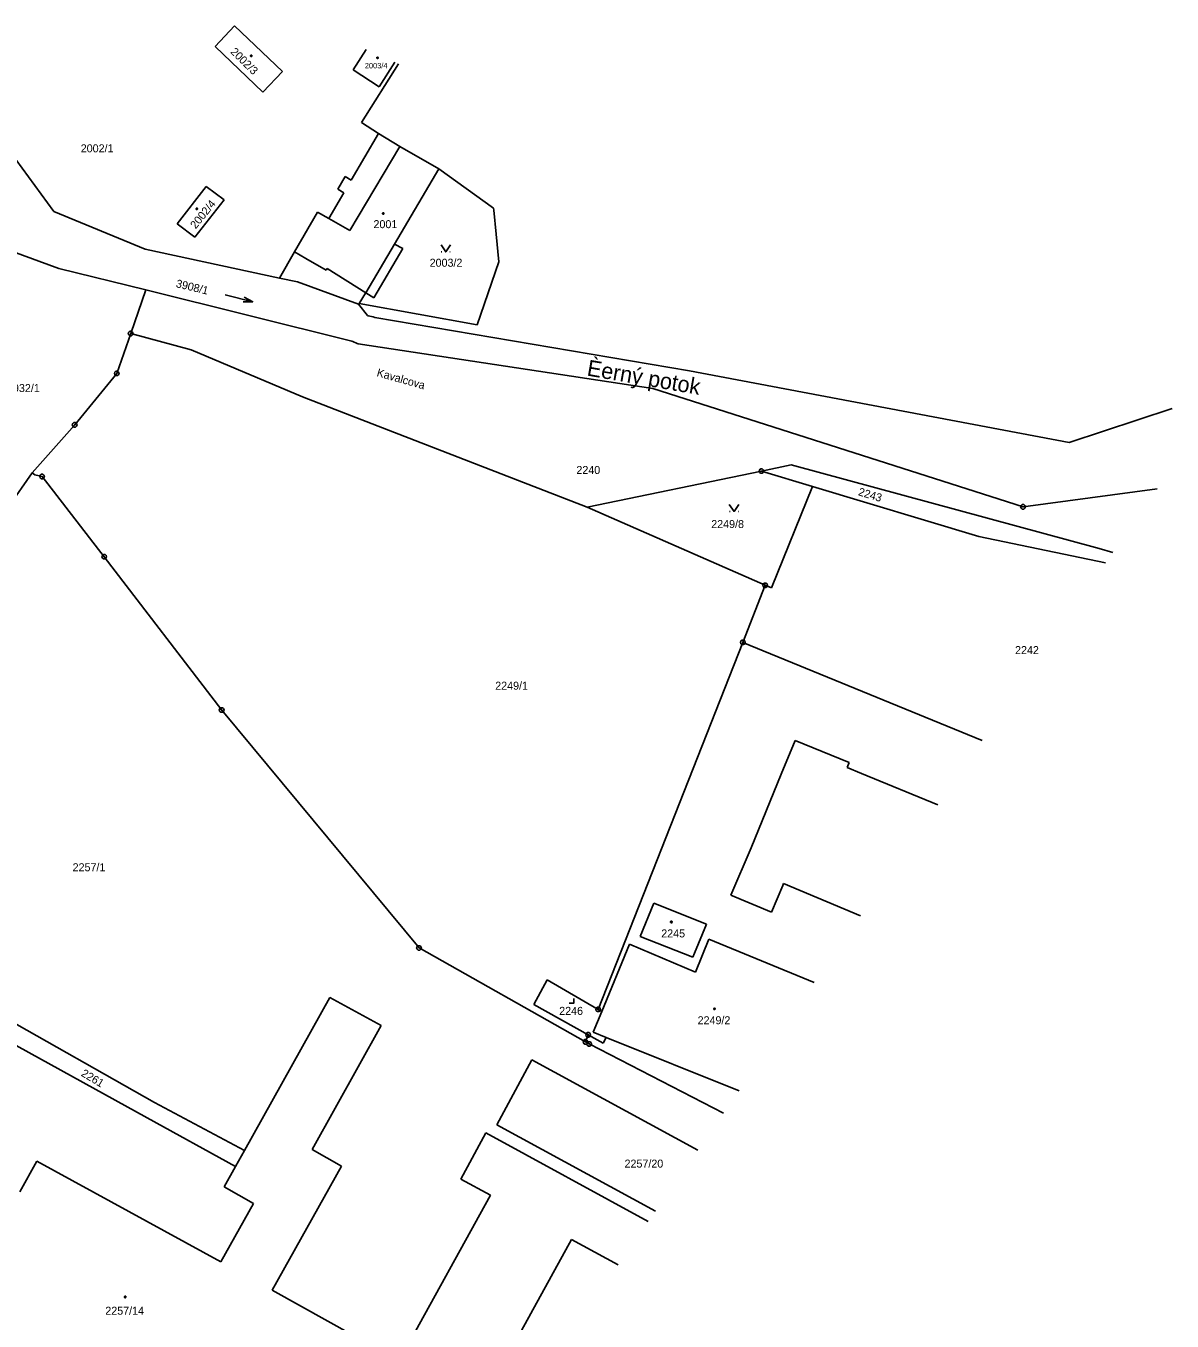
# Model space of a CAD drawing. Extents: x -528274 to -527531, y -1079304 to -1078580.
# Drawn here: x -527864 to -527620.7, y -1078911.9 to -1078636.8 of the extents above; entities that cross this region are included whole.
import ezdxf

# ---------------------------------------------------------------- set-up
doc = ezdxf.new("R2010")
doc.units = 0
doc.layers.add('katastrální mapa', color=7, linetype='Continuous')

msp = doc.modelspace()

# ---------------------------------------------------------------- linework, layer by layer
at = {"layer": 'katastrální mapa'}
for p, q in [((-527823.8, -1078641.21), (-527819.71, -1078636.82)), ((-527819.71, -1078636.82), (-527809.51, -1078646.52)), ((-527813.68, -1078650.87), (-527823.8, -1078641.21)), ((-527794.54, -1078646.16), (-527791.74, -1078641.84)), ((-527784.88, -1078644.89), (-527792.77, -1078657.34)), ((-527785.66, -1078644.54), (-527788.99, -1078649.73)), ((-527809.51, -1078646.52), (-527813.68, -1078650.87)), ((-527788.99, -1078649.73), (-527794.54, -1078646.16)), ((-527874.15, -1078654.27), (-527858.07, -1078676.23)), ((-527792.77, -1078657.34), (-527789.17, -1078659.65)), ((-527794.92, -1078669.55), (-527789.17, -1078659.65)), ((-527789.17, -1078659.65), (-527784.61, -1078662.4)), ((-527795.21, -1078680.24), (-527784.61, -1078662.4)), ((-527784.61, -1078662.4), (-527776.34, -1078667.2)), ((-527776.34, -1078667.2), (-527785.75, -1078683.15)), ((-527764.72, -1078675.54), (-527776.34, -1078667.2)), ((-527797.77, -1078671.52), (-527796.2, -1078668.81)), ((-527796.2, -1078668.81), (-527794.92, -1078669.55)), ((-527831.85, -1078678.83), (-527825.7, -1078670.92)), ((-527825.7, -1078670.92), (-527821.93, -1078673.78)), ((-527799.68, -1078677.73), (-527796.5, -1078672.26)), ((-527796.5, -1078672.26), (-527797.77, -1078671.52)), ((-527821.93, -1078673.78), (-527828.11, -1078681.68)), ((-527764.68, -1078675.95), (-527764.72, -1078675.54)), ((-527858.07, -1078676.23), (-527838.69, -1078684.25)), ((-527806.97, -1078684.81), (-527802.12, -1078676.36)), ((-527802.12, -1078676.36), (-527799.68, -1078677.73)), ((-527795.21, -1078680.24), (-527799.68, -1078677.73)), ((-527764.17, -1078681.04), (-527764.68, -1078675.95)), ((-527828.11, -1078681.68), (-527831.85, -1078678.83)), ((-527763.59, -1078686.89), (-527764.17, -1078681.04)), ((-527785.75, -1078683.15), (-527791.85, -1078693.49)), ((-527785.75, -1078683.15), (-527783.99, -1078684.07)), ((-527856.97, -1078688.3), (-527866.85, -1078684.72)), ((-527838.69, -1078684.25), (-527810.16, -1078690.36)), ((-527810.16, -1078690.36), (-527806.97, -1078684.81)), ((-527804.59, -1078686.18), (-527806.97, -1078684.81)), ((-527800.23, -1078688.72), (-527804.59, -1078686.18)), ((-527783.99, -1078684.07), (-527790.11, -1078694.59)), ((-527775.83, -1078684.83), (-527775.73, -1078684.83)), ((-527774.03, -1078684.83), (-527773.93, -1078684.83)), ((-527838.52, -1078692.88), (-527856.97, -1078688.3)), ((-527800.23, -1078688.72), (-527800.03, -1078688.36)), ((-527800.03, -1078688.36), (-527791.85, -1078693.49)), ((-527768.2, -1078700.28), (-527763.59, -1078686.89)), ((-527806.37, -1078691.17), (-527810.16, -1078690.36)), ((-527793.39, -1078695.94), (-527806.37, -1078691.17)), ((-527841.75, -1078702.14), (-527838.52, -1078692.88)), ((-527838.52, -1078692.88), (-527794.83, -1078703.76)), ((-527821.66, -1078693.92), (-527815.84, -1078695.38)), ((-527791.89, -1078693.56), (-527793.28, -1078695.76)), ((-527791.85, -1078693.49), (-527791.89, -1078693.56)), ((-527790.11, -1078694.59), (-527791.85, -1078693.49)), ((-527793.28, -1078695.76), (-527793.39, -1078695.94)), ((-527793.39, -1078695.94), (-527791.48, -1078698.33)), ((-527793.28, -1078695.76), (-527768.2, -1078700.28)), ((-527791.48, -1078698.33), (-527791.31, -1078698.37)), ((-527791.31, -1078698.37), (-527790.27, -1078698.62)), ((-527790.27, -1078698.62), (-527789.92, -1078698.71)), ((-527789.92, -1078698.71), (-527723.14, -1078710.07)), ((-527844.71, -1078710.62), (-527841.75, -1078702.14)), ((-527841.87, -1078702.14), (-527841.63, -1078702.14)), ((-527828.93, -1078705.6), (-527841.75, -1078702.14)), ((-527805.27, -1078715.6), (-527828.93, -1078705.6)), ((-527794.83, -1078703.76), (-527794.61, -1078703.85)), ((-527794.61, -1078703.85), (-527793.7, -1078704.24)), ((-527793.7, -1078704.24), (-527793.43, -1078704.35)), ((-527793.43, -1078704.35), (-527730.93, -1078713.79)), ((-527844.71, -1078710.62), (-527853.64, -1078721.55)), ((-527844.83, -1078710.62), (-527844.59, -1078710.62)), ((-527723.14, -1078710.07), (-527642.54, -1078725.25)), ((-527730.93, -1078713.79), (-527652.33, -1078738.95)), ((-527744.86, -1078739.03), (-527805.27, -1078715.6)), ((-527642.54, -1078725.25), (-527620.69, -1078718.06)), ((-527853.64, -1078721.55), (-527862.64, -1078731.72)), ((-527853.76, -1078721.55), (-527853.52, -1078721.55)), ((-527707.86, -1078731.36), (-527701.52, -1078730.04)), ((-527636.16, -1078747.81), (-527701.52, -1078730.04)), ((-527867.72, -1078738.94), (-527862.64, -1078731.72)), ((-527862.64, -1078731.72), (-527862.11, -1078732.12)), ((-527862.11, -1078732.12), (-527860.56, -1078732.51)), ((-527860.68, -1078732.51), (-527860.44, -1078732.51)), ((-527860.56, -1078732.51), (-527847.35, -1078749.55)), ((-527744.86, -1078739.03), (-527707.86, -1078731.36)), ((-527707.98, -1078731.36), (-527707.74, -1078731.36)), ((-527707.86, -1078731.36), (-527697.04, -1078734.64)), ((-527697.04, -1078734.64), (-527705.76, -1078756.16)), ((-527697.04, -1078734.64), (-527661.74, -1078745.23)), ((-527652.33, -1078738.95), (-527623.88, -1078735.11)), ((-527652.45, -1078738.95), (-527652.21, -1078738.95)), ((-527707.06, -1078755.61), (-527744.86, -1078739.03)), ((-527714.63, -1078739.93), (-527714.53, -1078739.93)), ((-527712.83, -1078739.93), (-527712.73, -1078739.93)), ((-527661.74, -1078745.23), (-527634.82, -1078750.87)), ((-527847.47, -1078749.55), (-527847.23, -1078749.55)), ((-527847.35, -1078749.55), (-527822.43, -1078782.1)), ((-527633.29, -1078748.65), (-527636.16, -1078747.81)), ((-527707.06, -1078755.61), (-527711.81, -1078767.73)), ((-527707.18, -1078755.61), (-527706.94, -1078755.61)), ((-527705.76, -1078756.16), (-527707.06, -1078755.61)), ((-527711.81, -1078767.73), (-527742.5, -1078845.67)), ((-527711.93, -1078767.73), (-527711.69, -1078767.73)), ((-527711.81, -1078767.73), (-527661.01, -1078788.59)), ((-527822.55, -1078782.1), (-527822.31, -1078782.1)), ((-527822.43, -1078782.1), (-527780.54, -1078832.62)), ((-527703.65, -1078795.72), (-527700.73, -1078788.57)), ((-527700.73, -1078788.57), (-527689.23, -1078793.27)), ((-527689.23, -1078793.27), (-527689.66, -1078794.33)), ((-527710.06, -1078811.38), (-527703.65, -1078795.72)), ((-527689.66, -1078794.33), (-527686.65, -1078795.56)), ((-527686.65, -1078795.56), (-527670.44, -1078802.19)), ((-527714.35, -1078821.4), (-527710.06, -1078811.38)), ((-527916.26, -1078820.33), (-527836.7, -1078865.44)), ((-527705.73, -1078825.02), (-527714.35, -1078821.4)), ((-527703.34, -1078819.36), (-527705.73, -1078825.02)), ((-527703.17, -1078818.96), (-527703.34, -1078819.36)), ((-527686.84, -1078825.82), (-527703.17, -1078818.96)), ((-527733.59, -1078830.21), (-527730.67, -1078823.13)), ((-527730.67, -1078823.13), (-527719.53, -1078827.54)), ((-527918.51, -1078824.42), (-527838.26, -1078868.7)), ((-527719.53, -1078827.54), (-527722.08, -1078833.74)), ((-527741.77, -1078846.09), (-527735.9, -1078831.82)), ((-527735.9, -1078831.82), (-527721.88, -1078837.74)), ((-527722.43, -1078834.59), (-527733.59, -1078830.21)), ((-527721.88, -1078837.74), (-527719, -1078830.73)), ((-527719, -1078830.73), (-527696.66, -1078839.97)), ((-527780.66, -1078832.62), (-527780.42, -1078832.62)), ((-527780.54, -1078832.62), (-527745.22, -1078852.56)), ((-527722.08, -1078833.74), (-527722.43, -1078834.59)), ((-527756.16, -1078844.61), (-527753.35, -1078839.42)), ((-527753.35, -1078839.42), (-527742.5, -1078845.67)), ((-527799.48, -1078843.12), (-527817.58, -1078875.62)), ((-527788.61, -1078849.08), (-527799.48, -1078843.12)), ((-527756.16, -1078844.61), (-527744.63, -1078851.07)), ((-527741.77, -1078846.09), (-527743.58, -1078850.49)), ((-527742.62, -1078845.67), (-527742.38, -1078845.67)), ((-527742.5, -1078845.67), (-527741.77, -1078846.09)), ((-527803.23, -1078875.43), (-527788.61, -1078849.08)), ((-527744.63, -1078851.07), (-527745.22, -1078852.56)), ((-527744.75, -1078851.07), (-527744.51, -1078851.07)), ((-527744.63, -1078851.07), (-527741.47, -1078852.84)), ((-527743.58, -1078850.49), (-527740.8, -1078851.6)), ((-527740.8, -1078851.6), (-527741.47, -1078852.84)), ((-527712.62, -1078862.96), (-527740.8, -1078851.6)), ((-527745.34, -1078852.56), (-527745.1, -1078852.56)), ((-527745.22, -1078852.56), (-527744.43, -1078853.01)), ((-527744.55, -1078853.01), (-527744.31, -1078853.01)), ((-527744.43, -1078853.01), (-527715.93, -1078867.73)), ((-527756.59, -1078856.4), (-527764.02, -1078870.15)), ((-527721.39, -1078875.59), (-527756.59, -1078856.4)), ((-527836.7, -1078865.44), (-527817.58, -1078875.62)), ((-527838.26, -1078868.7), (-527819.47, -1078879)), ((-527764.02, -1078870.15), (-527730.35, -1078888.5)), ((-527766.35, -1078871.89), (-527771.66, -1078881.69)), ((-527731.87, -1078890.69), (-527766.35, -1078871.89)), ((-527817.58, -1078875.62), (-527819.47, -1078879)), ((-527796.99, -1078878.94), (-527803.23, -1078875.43)), ((-527861.67, -1078877.91), (-527865.29, -1078884.42)), ((-527822.64, -1078899.28), (-527861.67, -1078877.91)), ((-527819.47, -1078879), (-527821.9, -1078883.37)), ((-527811.7, -1078905.31), (-527796.99, -1078878.94)), ((-527771.66, -1078881.69), (-527765.36, -1078885.09)), ((-527821.9, -1078883.37), (-527815.66, -1078886.85)), ((-527815.66, -1078886.85), (-527822.64, -1078899.28)), ((-527765.36, -1078885.09), (-527784.77, -1078920.26)), ((-527767.53, -1078929.65), (-527748.19, -1078894.51)), ((-527748.19, -1078894.51), (-527738.28, -1078899.92)), ((-527784.77, -1078920.26), (-527811.7, -1078905.31))]:
    msp.add_line(p, q, dxfattribs=at)
for points in [[(-527816.15, -1078643.01), (-527816.05, -1078643.03), (-527816, -1078643.12), (-527815.98, -1078643.18), (-527816, -1078643.27), (-527816.08, -1078643.34), (-527816.15, -1078643.35), (-527816.24, -1078643.32), (-527816.3, -1078643.26), (-527816.32, -1078643.18), (-527816.3, -1078643.09), (-527816.22, -1078643.02)], [(-527789.36, -1078643.42), (-527789.26, -1078643.44), (-527789.21, -1078643.53), (-527789.19, -1078643.59), (-527789.21, -1078643.68), (-527789.29, -1078643.75), (-527789.36, -1078643.76), (-527789.45, -1078643.73), (-527789.51, -1078643.67), (-527789.53, -1078643.59), (-527789.51, -1078643.5), (-527789.43, -1078643.43)], [(-527827.72, -1078675.5), (-527827.62, -1078675.52), (-527827.57, -1078675.61), (-527827.55, -1078675.67), (-527827.57, -1078675.76), (-527827.65, -1078675.83), (-527827.72, -1078675.84), (-527827.81, -1078675.81), (-527827.87, -1078675.75), (-527827.89, -1078675.67), (-527827.87, -1078675.58), (-527827.79, -1078675.51)], [(-527788.13, -1078676.5), (-527788.03, -1078676.52), (-527787.98, -1078676.61), (-527787.96, -1078676.67), (-527787.98, -1078676.76), (-527788.06, -1078676.83), (-527788.13, -1078676.84), (-527788.22, -1078676.81), (-527788.28, -1078676.75), (-527788.3, -1078676.67), (-527788.28, -1078676.58), (-527788.2, -1078676.51)], [(-527841.6, -1078701.66), (-527841.35, -1078701.84), (-527841.25, -1078702.13), (-527841.35, -1078702.42), (-527841.6, -1078702.6), (-527841.91, -1078702.6), (-527842.16, -1078702.42), (-527842.26, -1078702.13), (-527842.16, -1078701.84), (-527841.91, -1078701.66)], [(-527844.56, -1078710.14), (-527844.31, -1078710.32), (-527844.21, -1078710.61), (-527844.31, -1078710.9), (-527844.56, -1078711.08), (-527844.87, -1078711.08), (-527845.12, -1078710.9), (-527845.22, -1078710.61), (-527845.12, -1078710.32), (-527844.87, -1078710.14)], [(-527853.49, -1078721.07), (-527853.24, -1078721.25), (-527853.14, -1078721.54), (-527853.24, -1078721.83), (-527853.49, -1078722.01), (-527853.8, -1078722.01), (-527854.05, -1078721.83), (-527854.15, -1078721.54), (-527854.05, -1078721.25), (-527853.8, -1078721.07)], [(-527860.41, -1078732.03), (-527860.16, -1078732.21), (-527860.06, -1078732.5), (-527860.16, -1078732.79), (-527860.41, -1078732.97), (-527860.72, -1078732.97), (-527860.97, -1078732.79), (-527861.07, -1078732.5), (-527860.97, -1078732.21), (-527860.72, -1078732.03)], [(-527707.71, -1078730.88), (-527707.46, -1078731.06), (-527707.36, -1078731.35), (-527707.46, -1078731.64), (-527707.71, -1078731.82), (-527708.02, -1078731.82), (-527708.27, -1078731.64), (-527708.37, -1078731.35), (-527708.27, -1078731.06), (-527708.02, -1078730.88)], [(-527652.18, -1078738.47), (-527651.93, -1078738.65), (-527651.83, -1078738.94), (-527651.93, -1078739.23), (-527652.18, -1078739.41), (-527652.49, -1078739.41), (-527652.74, -1078739.23), (-527652.84, -1078738.94), (-527652.74, -1078738.65), (-527652.49, -1078738.47)], [(-527847.2, -1078749.07), (-527846.95, -1078749.25), (-527846.85, -1078749.54), (-527846.95, -1078749.83), (-527847.2, -1078750.01), (-527847.51, -1078750.01), (-527847.76, -1078749.83), (-527847.86, -1078749.54), (-527847.76, -1078749.25), (-527847.51, -1078749.07)], [(-527706.91, -1078755.13), (-527706.66, -1078755.31), (-527706.56, -1078755.6), (-527706.66, -1078755.89), (-527706.91, -1078756.07), (-527707.22, -1078756.07), (-527707.47, -1078755.89), (-527707.57, -1078755.6), (-527707.47, -1078755.31), (-527707.22, -1078755.13)], [(-527711.66, -1078767.25), (-527711.41, -1078767.43), (-527711.31, -1078767.72), (-527711.41, -1078768.01), (-527711.66, -1078768.19), (-527711.97, -1078768.19), (-527712.22, -1078768.01), (-527712.32, -1078767.72), (-527712.22, -1078767.43), (-527711.97, -1078767.25)], [(-527822.28, -1078781.62), (-527822.03, -1078781.8), (-527821.93, -1078782.09), (-527822.03, -1078782.38), (-527822.28, -1078782.56), (-527822.59, -1078782.56), (-527822.84, -1078782.38), (-527822.94, -1078782.09), (-527822.84, -1078781.8), (-527822.59, -1078781.62)], [(-527726.99, -1078826.93), (-527726.89, -1078826.95), (-527726.84, -1078827.04), (-527726.82, -1078827.1), (-527726.84, -1078827.19), (-527726.92, -1078827.26), (-527726.99, -1078827.27), (-527727.08, -1078827.24), (-527727.14, -1078827.18), (-527727.16, -1078827.1), (-527727.14, -1078827.01), (-527727.06, -1078826.94)], [(-527780.39, -1078832.14), (-527780.14, -1078832.32), (-527780.04, -1078832.61), (-527780.14, -1078832.9), (-527780.39, -1078833.08), (-527780.7, -1078833.08), (-527780.95, -1078832.9), (-527781.05, -1078832.61), (-527780.95, -1078832.32), (-527780.7, -1078832.14)], [(-527742.35, -1078845.19), (-527742.1, -1078845.37), (-527742, -1078845.66), (-527742.1, -1078845.95), (-527742.35, -1078846.13), (-527742.66, -1078846.13), (-527742.91, -1078845.95), (-527743.01, -1078845.66), (-527742.91, -1078845.37), (-527742.66, -1078845.19)], [(-527717.85, -1078845.36), (-527717.75, -1078845.38), (-527717.7, -1078845.47), (-527717.68, -1078845.53), (-527717.7, -1078845.62), (-527717.78, -1078845.69), (-527717.85, -1078845.7), (-527717.94, -1078845.67), (-527718, -1078845.61), (-527718.02, -1078845.53), (-527718, -1078845.44), (-527717.92, -1078845.37)], [(-527744.48, -1078850.59), (-527744.23, -1078850.77), (-527744.13, -1078851.06), (-527744.23, -1078851.35), (-527744.48, -1078851.53), (-527744.79, -1078851.53), (-527745.04, -1078851.35), (-527745.14, -1078851.06), (-527745.04, -1078850.77), (-527744.79, -1078850.59)], [(-527745.07, -1078852.08), (-527744.82, -1078852.26), (-527744.72, -1078852.55), (-527744.82, -1078852.84), (-527745.07, -1078853.02), (-527745.38, -1078853.02), (-527745.63, -1078852.84), (-527745.73, -1078852.55), (-527745.63, -1078852.26), (-527745.38, -1078852.08)], [(-527744.28, -1078852.53), (-527744.03, -1078852.71), (-527743.93, -1078853), (-527744.03, -1078853.29), (-527744.28, -1078853.47), (-527744.59, -1078853.47), (-527744.84, -1078853.29), (-527744.94, -1078853), (-527744.84, -1078852.71), (-527744.59, -1078852.53)], [(-527842.91, -1078906.57), (-527842.81, -1078906.59), (-527842.76, -1078906.68), (-527842.74, -1078906.74), (-527842.76, -1078906.83), (-527842.84, -1078906.9), (-527842.91, -1078906.91), (-527843, -1078906.88), (-527843.06, -1078906.82), (-527843.08, -1078906.74), (-527843.06, -1078906.65), (-527842.98, -1078906.58)]]:
    msp.add_lwpolyline(points, close=True, dxfattribs=at)
for points in [[(-527775.88, -1078683.33), (-527774.88, -1078684.83), (-527773.88, -1078683.33)], [(-527817.66, -1078694.41), (-527815.84, -1078695.38), (-527817.9, -1078695.38)], [(-527714.68, -1078738.43), (-527713.68, -1078739.93), (-527712.68, -1078738.43)], [(-527748.69, -1078844.35), (-527747.69, -1078844.35), (-527747.69, -1078843.35)]]:
    msp.add_lwpolyline(points, dxfattribs=at)

# ---------------------------------------------------------------- texts
for s, height, rotation, p in [('2002/3', 1.7, 315.4706, (-527820.7, -1078642.46)), ('2002/4', 1.7, 51.0505, (-527827.95, -1078680.05)), ('3908/1', 1.7, 346.4103, (-527832.26, -1078692.27)), ('Èerný potok', 3.4, 350.1918, (-527745.05, -1078711.04)), ('Kavalcova', 1.7, 344.233, (-527789.64, -1078711.17)), ('2243', 1.7, 343.3163, (-527687.44, -1078736.46)), ('2261', 1.7, 329.107, (-527852.41, -1078859.69))]:
    msp.add_text(s, height=height, rotation=rotation, dxfattribs=at).set_placement(p)
for s, height, p in [('2003/4', 1.14, (-527792.05, -1078645.83)), ('2002/1', 1.7, (-527852.35, -1078663.67)), ('2001', 1.7, (-527790.21, -1078679.77)), ('2003/2', 1.7, (-527778.29, -1078687.96)), ('1932/1', 1.7, (-527868, -1078714.57)), ('2240', 1.7, (-527747.14, -1078731.97)), ('2249/8', 1.7, (-527718.52, -1078743.45)), ('2242', 1.7, (-527654.03, -1078770.22)), ('2249/1', 1.7, (-527764.37, -1078777.78)), ('2257/1', 1.7, (-527854.08, -1078816.33)), ('2245', 1.7, (-527729.13, -1078830.38)), ('2246', 1.7, (-527750.79, -1078846.83)), ('2249/2', 1.7, (-527721.41, -1078848.82)), ('2257/20', 1.7, (-527736.92, -1078879.26)), ('2257/14', 1.7, (-527847.14, -1078910.5))]:
    msp.add_text(s, height=height, dxfattribs=at).set_placement(p)

doc.saveas('drawing.dxf')
